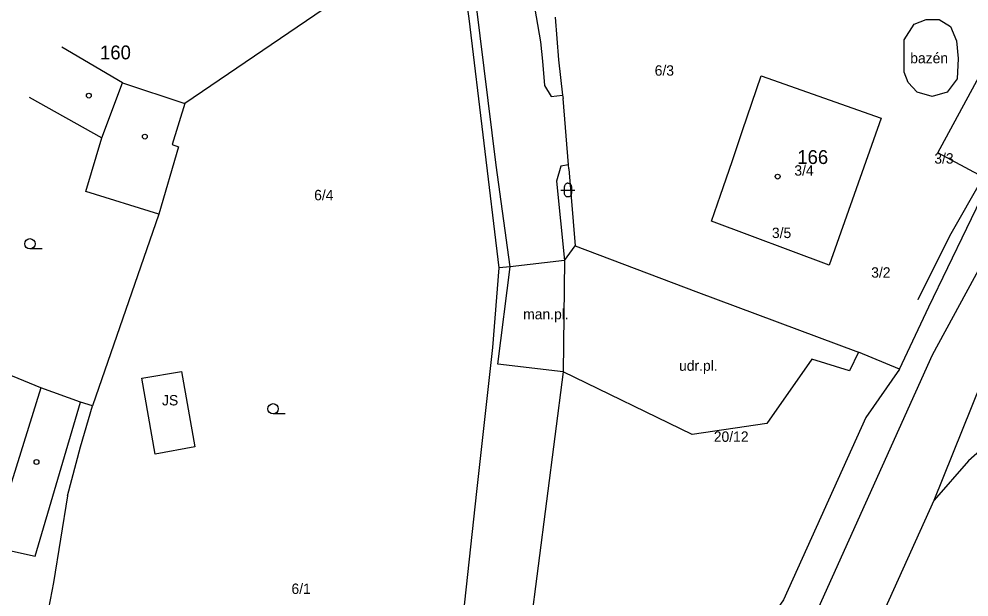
# Model space of a CAD drawing. Extents: x -836739 to -835945, y -1070775 to -1070126.
# Drawn here: x -836690.1 to -836621.5, y -1070398.7 to -1070357 of the extents above; entities that cross this region are included whole.
import ezdxf

# ---------------------------------------------------------------- set-up
doc = ezdxf.new("R2010")
doc.units = 0
for name, color, linetype in [('BodPole_mer', 7, 'Continuous'), ('Budovy_hranice', 7, 'Continuous'), ('Budovy_kody', 7, 'Continuous'), ('Doprava_hranice', 7, 'Continuous'), ('OstPloch_hranice', 7, 'Continuous'), ('OstPloch_kody', 7, 'Continuous'), ('RuianAdr_popis', 7, 'Continuous'), ('RuianPar_popis', 7, 'Continuous'), ('Stavby_hr_stav', 7, 'Continuous'), ('Stavby_kody', 7, 'Continuous'), ('Stavby_linie', 7, 'Continuous'), ('Vodstvo_hranice', 7, 'Continuous'), ('Vodstvo_kody', 7, 'Continuous'), ('Zelen_kody', 7, 'Continuous')]:
    doc.layers.add(name, color=color, linetype=linetype)

msp = doc.modelspace()

# ---------------------------------------------------------------- linework, layer by layer
at = {"layer": 'BodPole_mer'}
for p, q in [((-836624.56, -1070357), (-836624.56, -1070357)), ((-836623.62, -1070357), (-836623.62, -1070357)), ((-836625.43, -1070357.35), (-836625.43, -1070357.35)), ((-836622.81, -1070357.5), (-836622.81, -1070357.5)), ((-836652.43, -1070358.62), (-836652.43, -1070358.62)), ((-836626.16, -1070358.48), (-836626.16, -1070358.48)), ((-836622.38, -1070358.55), (-836622.38, -1070358.55)), ((-836652.29, -1070360.01), (-836652.29, -1070360.01)), ((-836651.13, -1070359.92), (-836651.13, -1070359.92)), ((-836622.26, -1070359.83), (-836622.26, -1070359.83)), ((-836636.48, -1070361.06), (-836636.48, -1070361.06)), ((-836626.15, -1070360.81), (-836626.15, -1070360.81)), ((-836682.62, -1070361.58), (-836682.62, -1070361.58)), ((-836652.13, -1070361.76), (-836652.13, -1070361.76)), ((-836625.88, -1070361.56), (-836625.88, -1070361.56)), ((-836622.32, -1070361.28), (-836622.32, -1070361.28)), ((-836650.83, -1070362.47), (-836650.83, -1070362.47)), ((-836625.21, -1070362.26), (-836625.21, -1070362.26)), ((-836623.06, -1070362.24), (-836623.06, -1070362.24)), ((-836678.12, -1070363.07), (-836678.12, -1070363.07)), ((-836651.65, -1070362.56), (-836651.65, -1070362.56)), ((-836650.8, -1070362.7), (-836650.8, -1070362.7)), ((-836624.14, -1070362.56), (-836624.14, -1070362.56)), ((-836627.82, -1070364.13), (-836627.82, -1070364.13)), ((-836637.83, -1070365.02), (-836637.83, -1070365.02)), ((-836684.11, -1070365.55), (-836684.11, -1070365.55)), ((-836679.04, -1070366.04), (-836679.04, -1070366.04)), ((-836678.57, -1070366.2), (-836678.57, -1070366.2)), ((-836623.72, -1070366.64), (-836623.72, -1070366.64)), ((-836638.59, -1070367.26), (-836638.59, -1070367.26)), ((-836655.63, -1070367.52), (-836655.63, -1070367.52)), ((-836650.96, -1070367.6), (-836650.96, -1070367.6)), ((-836650.41, -1070367.5), (-836650.41, -1070367.5)), ((-836650.39, -1070367.79), (-836650.39, -1070367.79)), ((-836651.27, -1070368.67), (-836651.27, -1070368.67)), ((-836685.28, -1070369.42), (-836685.28, -1070369.42)), ((-836639.43, -1070369.7), (-836639.43, -1070369.7)), ((-836680, -1070371.07), (-836680, -1070371.07)), ((-836640.07, -1070371.58), (-836640.07, -1070371.58)), ((-836622.88, -1070372.65), (-836622.88, -1070372.65)), ((-836649.92, -1070373.36), (-836649.92, -1070373.36)), ((-836654.63, -1070374.88), (-836654.63, -1070374.88)), ((-836650.69, -1070374.42), (-836650.69, -1070374.42)), ((-836631.58, -1070374.75), (-836631.58, -1070374.75)), ((-836655.41, -1070374.93), (-836655.41, -1070374.93)), ((-836641.2, -1070376.64), (-836641.2, -1070376.64)), ((-836625.16, -1070377.26), (-836625.16, -1070377.26)), ((-836624.37, -1070377.75), (-836624.37, -1070377.75)), ((-836655.87, -1070380.69), (-836655.87, -1070380.69)), ((-836629.46, -1070381.04), (-836629.46, -1070381.04)), ((-836632.83, -1070381.55), (-836632.83, -1070381.55)), ((-836624.1, -1070381.23), (-836624.1, -1070381.23)), ((-836678.37, -1070382.42), (-836678.37, -1070382.42)), ((-836655.5, -1070381.91), (-836655.5, -1070381.91)), ((-836630.1, -1070382.38), (-836630.1, -1070382.38)), ((-836626.49, -1070382.25), (-836626.49, -1070382.25)), ((-836681.23, -1070382.92), (-836681.23, -1070382.92)), ((-836650.79, -1070382.45), (-836650.79, -1070382.45)), ((-836688.53, -1070383.6), (-836688.53, -1070383.6)), ((-836685.66, -1070384.65), (-836685.66, -1070384.65)), ((-836684.8, -1070384.91), (-836684.8, -1070384.91)), ((-836628.93, -1070385.76), (-836628.93, -1070385.76)), ((-836636.09, -1070386.19), (-836636.09, -1070386.19)), ((-836641.48, -1070386.97), (-836641.48, -1070386.97)), ((-836685.67, -1070387.88), (-836685.67, -1070387.88)), ((-836677.4, -1070387.88), (-836677.4, -1070387.88)), ((-836680.27, -1070388.39), (-836680.27, -1070388.39)), ((-836621.52, -1070388.89), (-836621.52, -1070388.89)), ((-836657.04, -1070391.1), (-836657.04, -1070391.1)), ((-836686.61, -1070391.4), (-836686.61, -1070391.4)), ((-836624, -1070391.72), (-836624, -1070391.72)), ((-836688.94, -1070395.76), (-836688.94, -1070395.76)), ((-836687.61, -1070397.67), (-836687.61, -1070397.67))]:
    msp.add_line(p, q, dxfattribs=at)
at = {"layer": 'Budovy_hranice'}
for p, q in [((-836682.62, -1070361.58), (-836687.01, -1070359.01)), ((-836689.38, -1070362.61), (-836684.11, -1070365.55))]:
    msp.add_line(p, q, dxfattribs=at)
for points in [[(-836631.58, -1070374.75), (-836640.07, -1070371.58), (-836639.43, -1070369.7), (-836638.59, -1070367.26), (-836637.83, -1070365.02), (-836636.48, -1070361.06), (-836627.82, -1070364.13), (-836631.58, -1070374.75)], [(-836679.04, -1070366.04), (-836678.57, -1070366.2), (-836680, -1070371.07), (-836685.28, -1070369.42), (-836684.11, -1070365.55), (-836682.62, -1070361.58), (-836678.12, -1070363.07), (-836679.04, -1070366.04)], [(-836688.94, -1070395.76), (-836685.66, -1070384.65), (-836688.53, -1070383.6), (-836692.11, -1070395.08), (-836688.94, -1070395.76)]]:
    msp.add_lwpolyline(points, dxfattribs=at)
at = {"layer": 'Budovy_kody'}
for centre in [(-836685.06, -1070362.5), (-836681.01, -1070365.46), (-836635.3, -1070368.35), (-836688.84, -1070388.97)]:
    msp.add_circle(centre, 0.175, dxfattribs=at)
at = {"layer": 'Doprava_hranice'}
msp.add_line((-836624, -1070391.72), (-836618.13, -1070377.15), dxfattribs=at)
for points in [[(-836637.13, -1070410.36), (-836632.54, -1070399.93), (-836624.1, -1070381.23), (-836615.6, -1070365.58), (-836607.14, -1070355.56), (-836596.81, -1070346.2), (-836590.03, -1070339.5), (-836589.31, -1070338.79), (-836589.07, -1070337.69), (-836589.06, -1070336.43), (-836589.28, -1070334.96), (-836590.73, -1070333.14), (-836591.73, -1070332.35), (-836593.66, -1070331.61), (-836605.86, -1070329.36), (-836624.31, -1070324.48)], [(-836650.41, -1070367.5), (-836650.96, -1070367.6), (-836651.27, -1070368.67), (-836650.69, -1070374.42), (-836654.63, -1070374.88), (-836655.63, -1070367.52), (-836657.37, -1070353.48), (-836657.73, -1070349.93), (-836659.71, -1070341.92), (-836662.66, -1070333.84), (-836664.35, -1070331.52), (-836667.79, -1070329.01), (-836670.76, -1070327.26), (-836677.72, -1070331.28), (-836681.67, -1070335.86), (-836683.38, -1070337.84)], [(-836653.47, -1070346.76), (-836654.39, -1070347.34), (-836652.43, -1070358.62), (-836652.29, -1070360.01), (-836652.13, -1070361.76), (-836651.65, -1070362.56), (-836650.83, -1070362.47)], [(-836607.42, -1070377.87), (-836615.46, -1070383.56), (-836621.52, -1070388.89), (-836624, -1070391.72)], [(-836629.46, -1070381.04), (-836630.1, -1070382.38), (-836632.83, -1070381.55), (-836636.09, -1070386.19), (-836641.48, -1070386.97), (-836650.79, -1070382.45), (-836653.8, -1070405.82), (-836653.8, -1070413.64), (-836660.69, -1070431.93), (-836661.86, -1070443.82), (-836659.27, -1070448.73), (-836656.69, -1070455.24), (-836654.9, -1070458.11)], [(-836626.49, -1070382.25), (-836628.93, -1070385.76), (-836634.87, -1070398.93), (-836637.79, -1070403.09), (-836640.55, -1070405.67), (-836641.83, -1070408.47), (-836641.31, -1070415.5), (-836651.36, -1070445.15), (-836654.9, -1070458.11), (-836657.15, -1070469.1)], [(-836636.57, -1070420.39), (-836634.38, -1070415.61), (-836632.33, -1070410.21), (-836631.12, -1070407.53), (-836630.16, -1070405.38), (-836624, -1070391.72)]]:
    msp.add_lwpolyline(points, dxfattribs=at)
at = {"layer": 'OstPloch_hranice'}
for p, q in [((-836680, -1070371.07), (-836684.8, -1070384.91)), ((-836650.69, -1070374.42), (-836649.92, -1070373.36)), ((-836654.63, -1070374.88), (-836655.41, -1070374.93)), ((-836626.49, -1070382.25), (-836629.46, -1070381.04))]:
    msp.add_line(p, q, dxfattribs=at)
msp.add_lwpolyline([(-836650.69, -1070374.42), (-836650.79, -1070382.45), (-836655.5, -1070381.91), (-836654.63, -1070374.88)], dxfattribs=at)
at = {"layer": 'OstPloch_kody'}
for p, q in [((-836650.95, -1070369.32), (-836649.95, -1070369.32)), ((-836650.7, -1070369.57), (-836650.7, -1070369.07)), ((-836650.2, -1070369.07), (-836650.2, -1070369.57)), ((-836688.435, -1070373.58), (-836689.31, -1070373.58)), ((-836670.875, -1070385.5), (-836671.75, -1070385.5))]:
    msp.add_line(p, q, dxfattribs=at)
for points in [[(-836650.45, -1070368.82), (-836650.495, -1070368.824), (-836650.542, -1070368.838), (-836650.587, -1070368.861), (-836650.627, -1070368.893), (-836650.659, -1070368.933), (-836650.682, -1070368.978), (-836650.696, -1070369.025), (-836650.7, -1070369.07)], [(-836650.45, -1070368.82), (-836650.405, -1070368.824), (-836650.358, -1070368.838), (-836650.313, -1070368.861), (-836650.273, -1070368.893), (-836650.241, -1070368.933), (-836650.218, -1070368.978), (-836650.204, -1070369.025), (-836650.2, -1070369.07)], [(-836650.45, -1070369.82), (-836650.495, -1070369.816), (-836650.542, -1070369.802), (-836650.587, -1070369.779), (-836650.627, -1070369.747), (-836650.659, -1070369.707), (-836650.682, -1070369.662), (-836650.696, -1070369.615), (-836650.7, -1070369.57)], [(-836650.2, -1070369.57), (-836650.204, -1070369.615), (-836650.218, -1070369.662), (-836650.241, -1070369.707), (-836650.273, -1070369.747), (-836650.313, -1070369.779), (-836650.358, -1070369.802), (-836650.405, -1070369.816), (-836650.45, -1070369.82)]]:
    msp.add_lwpolyline(points, dxfattribs=at)
for centre in [(-836689.31, -1070373.205), (-836671.75, -1070385.125)]:
    msp.add_ellipse(centre, major_axis=(0.375, 0), ratio=0.999999, dxfattribs=at)
at = {"layer": 'RuianAdr_popis'}
for p, q in [((-836684.25, -1070359.88), (-836684.25, -1070359.88)), ((-836633.88, -1070367.44), (-836633.88, -1070367.44))]:
    msp.add_line(p, q, dxfattribs=at)
at = {"layer": 'RuianPar_popis'}
for p, q in [((-836644.18, -1070361.06), (-836644.18, -1070361.06)), ((-836623.98, -1070367.41), (-836623.98, -1070367.41)), ((-836634.09, -1070368.28), (-836634.09, -1070368.28)), ((-836668.78, -1070370.06), (-836668.78, -1070370.06)), ((-836635.71, -1070372.79), (-836635.71, -1070372.79)), ((-836628.54, -1070375.65), (-836628.54, -1070375.65)), ((-836639.91, -1070387.51), (-836639.91, -1070387.51)), ((-836670.42, -1070398.5), (-836670.42, -1070398.5))]:
    msp.add_line(p, q, dxfattribs=at)
at = {"layer": 'Stavby_hr_stav'}
for points in [[(-836620.44, -1070368.4), (-836623.72, -1070366.64), (-836620.75, -1070361.12), (-836620.48, -1070361.27), (-836617.48, -1070362.88), (-836617.61, -1070363.13), (-836620.44, -1070368.4)], [(-836677.4, -1070387.88), (-836680.27, -1070388.39), (-836681.23, -1070382.92), (-836678.37, -1070382.42), (-836677.4, -1070387.88)]]:
    msp.add_lwpolyline(points, dxfattribs=at)
at = {"layer": 'Stavby_linie'}
for p, q in [((-836658.62, -1070349.8), (-836678.12, -1070363.07)), ((-836650.39, -1070367.79), (-836649.92, -1070373.36)), ((-836655.87, -1070380.69), (-836655.41, -1070374.93))]:
    msp.add_line(p, q, dxfattribs=at)
for points in [[(-836655.41, -1070374.93), (-836657.58, -1070356.93), (-836658.62, -1070349.8)], [(-836651.38, -1070356.83), (-836651.13, -1070359.92), (-836650.83, -1070362.47), (-836650.8, -1070362.7)], [(-836650.39, -1070367.79), (-836650.41, -1070367.5), (-836650.8, -1070362.7)], [(-836626.49, -1070382.25), (-836624.37, -1070377.75), (-836620.25, -1070369.24), (-836616.94, -1070363.53)], [(-836620.44, -1070368.4), (-836622.88, -1070372.65), (-836625.16, -1070377.26)], [(-836649.92, -1070373.36), (-836641.2, -1070376.64), (-836629.46, -1070381.04)], [(-836688.53, -1070383.6), (-836705.37, -1070376.67), (-836708.22, -1070375.44)], [(-836659.17, -1070411.22), (-836657.89, -1070399.1), (-836657.04, -1070391.1), (-836655.87, -1070380.69)], [(-836686.61, -1070391.4), (-836685.67, -1070387.88), (-836684.8, -1070384.91), (-836685.66, -1070384.65)], [(-836686.61, -1070391.4), (-836687.61, -1070397.67), (-836688.21, -1070400.8), (-836689.33, -1070406.69), (-836688.98, -1070419.42), (-836689, -1070419.82)]]:
    msp.add_lwpolyline(points, dxfattribs=at)
at = {"layer": 'Vodstvo_hranice'}
msp.add_lwpolyline([(-836622.26, -1070359.83), (-836622.32, -1070361.28), (-836623.06, -1070362.24), (-836624.14, -1070362.56), (-836625.21, -1070362.26), (-836625.88, -1070361.56), (-836626.15, -1070360.81), (-836626.16, -1070358.48), (-836625.43, -1070357.35), (-836624.56, -1070357), (-836623.62, -1070357), (-836622.81, -1070357.5), (-836622.38, -1070358.55), (-836622.26, -1070359.83)], dxfattribs=at)

# ---------------------------------------------------------------- texts
at = {"layer": 'OstPloch_kody'}
msp.add_text('man.pl.', height=0.75, dxfattribs=at).set_placement((-836653.68, -1070378.66))
at = {"layer": 'RuianAdr_popis'}
for s, p in [('160', (-836684.25, -1070359.88)), ('166', (-836633.88, -1070367.44))]:
    msp.add_text(s, height=1, dxfattribs=at).set_placement(p)
at = {"layer": 'RuianPar_popis'}
for s, p in [('6/3', (-836644.18, -1070361.06)), ('3/3', (-836623.98, -1070367.41)), ('3/4', (-836634.09, -1070368.28)), ('6/4', (-836668.78, -1070370.06)), ('3/5', (-836635.71, -1070372.79)), ('3/2', (-836628.54, -1070375.65)), ('20/12', (-836639.91, -1070387.51)), ('6/1', (-836670.42, -1070398.5))]:
    msp.add_text(s, height=0.75, dxfattribs=at).set_placement(p)
at = {"layer": 'Stavby_kody'}
msp.add_text('JS', height=0.75, dxfattribs=at).set_placement((-836679.77, -1070384.88))
at = {"layer": 'Vodstvo_kody'}
msp.add_text('bazén', height=0.75, dxfattribs=at).set_placement((-836625.72, -1070360.16))
at = {"layer": 'Zelen_kody'}
msp.add_text('udr.pl.', height=0.75, dxfattribs=at).set_placement((-836642.42, -1070382.38))

doc.saveas('drawing.dxf')
